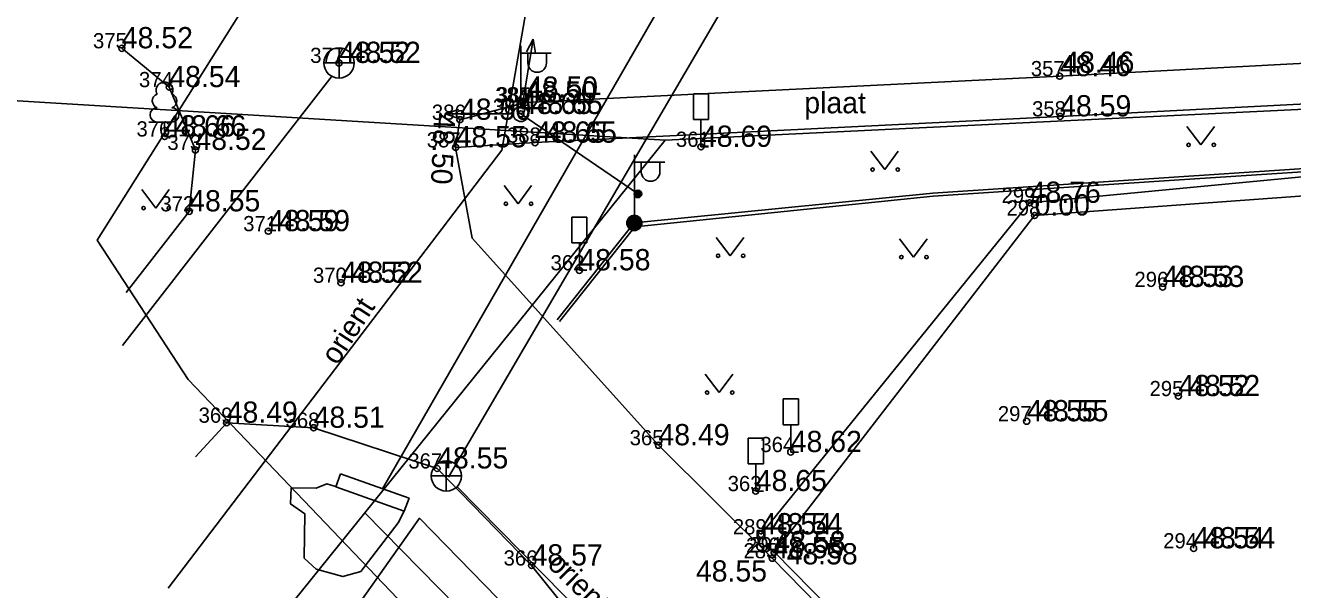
# Model space of a CAD drawing. Extents: x 640876 to 641418, y 6455595 to 6456085.
# Drawn here: x 641063.77 to 641105.51, y 6455977.11 to 6455995.7 of the extents above; entities that cross this region are included whole.
import ezdxf

# ---------------------------------------------------------------- set-up
doc = ezdxf.new("R2010")
doc.units = 0
for name, color, linetype in [('AED', 7, 'Continuous'), ('HALJASTUS', 7, 'Continuous'), ('KKAEV', 7, 'Continuous'), ('KORGUS', 7, 'Continuous'), ('KPKAABEL', 7, 'Continuous'), ('KTRASS', 7, 'Continuous'), ('LIIKLUS', 7, 'Continuous'), ('MOOTKORG', 7, 'Continuous'), ('MOOTMPUNKT', 7, 'Continuous'), ('MOOTNR', 7, 'Continuous'), ('MOOTPIIR', 7, 'Continuous'), ('MPKAABEL', 7, 'Continuous'), ('MPOHULIIN', 7, 'Continuous'), ('PIIR', 7, 'Continuous'), ('POST', 7, 'Continuous'), ('PUU', 7, 'Continuous'), ('SKKAEV', 7, 'Continuous'), ('SKTRASS', 7, 'Continuous'), ('TEE', 7, 'Continuous'), ('TRUUP', 7, 'Continuous'), ('VEEKOGU', 7, 'Continuous')]:
    doc.layers.add(name, color=color, linetype=linetype)

msp = doc.modelspace()

# ---------------------------------------------------------------- linework, layer by layer
at = {"layer": 'AED'}
for p, q in [((641087.869, 6455979.056), (641087.869, 6455978.806)), ((641087.869, 6455979.056), (641088.119, 6455979.056)), ((641088.119, 6455979.056), (641088.119, 6455978.806)), ((641087.869, 6455978.806), (641088.119, 6455978.806))]:
    msp.add_line(p, q, dxfattribs=at)
for points in [[(641087.994, 6455978.931), (641096.846, 6455989.854), (641117.445, 6455991.822), (641132.506, 6455992.659), (641144.443, 6455993.343), (641153.401, 6455993.722)], [(641083.796, 6455973.39), (641083.187, 6455972.863), (641076.75, 6455979.46), (641073.84, 6455975.34)], [(641149.47, 6455968.396), (641146.41, 6455975.887), (641122.837, 6455974.363), (641106.897, 6455973.309), (641093.89, 6455972.505), (641088.371, 6455978.142)]]:
    msp.add_lwpolyline(points, dxfattribs=at)
at = {"layer": 'HALJASTUS'}
for p, q in [((641102.021, 6455992.369), (641102.484, 6455991.763)), ((641102.484, 6455991.763), (641102.93, 6455992.369)), ((641091.612, 6455991.558), (641092.075, 6455990.951)), ((641092.075, 6455990.951), (641092.52, 6455991.558)), ((641079.535, 6455990.431), (641079.998, 6455989.824)), ((641079.998, 6455989.824), (641080.444, 6455990.431)), ((641067.6, 6455990.291), (641068.063, 6455989.684)), ((641068.063, 6455989.684), (641068.509, 6455990.291)), ((641086.52, 6455988.717), (641086.983, 6455988.111)), ((641086.983, 6455988.111), (641087.429, 6455988.717)), ((641092.558, 6455988.672), (641093.021, 6455988.066)), ((641093.021, 6455988.066), (641093.467, 6455988.672)), ((641086.159, 6455984.209), (641086.622, 6455983.602)), ((641086.622, 6455983.602), (641087.068, 6455984.209))]:
    msp.add_line(p, q, dxfattribs=at)
for centre in [(641102.083, 6455991.763), (641102.912, 6455991.763), (641091.674, 6455990.951), (641092.503, 6455990.951), (641067.662, 6455989.684), (641068.491, 6455989.684), (641079.597, 6455989.824), (641080.426, 6455989.824), (641086.582, 6455988.111), (641087.411, 6455988.111), (641092.62, 6455988.066), (641093.449, 6455988.066), (641086.221, 6455983.602), (641087.05, 6455983.602)]:
    msp.add_circle(centre, 0.055, dxfattribs=at)
at = {"layer": 'KKAEV'}
for p, q in [((641074.101, 6455993.964), (641074.101, 6455994.964)), ((641073.601, 6455994.464), (641074.601, 6455994.464))]:
    msp.add_line(p, q, dxfattribs=at)
msp.add_circle((641074.101, 6455994.464), 0.5, dxfattribs=at)
at = {"layer": 'KORGUS'}
for centre in [(641074.101, 6455994.464), (641097.835, 6455994.027), (641080.246, 6455993.162), (641080.092, 6455992.782), (641078.083, 6455992.591), (641068.353, 6455992.04), (641080.556, 6455991.837), (641071.768, 6455988.92), (641074.166, 6455987.22), (641101.223, 6455987.082), (641101.745, 6455983.485), (641096.748, 6455982.656), (641087.994, 6455978.931), (641088.371, 6455978.142), (641088.438, 6455978.34), (641102.244, 6455978.47)]:
    msp.add_circle(centre, 0.1, dxfattribs=at)
at = {"layer": 'KPKAABEL'}
msp.add_lwpolyline([(641068.476, 6455977.159), (641079.463, 6455991.588), (641081.251, 6456001.896), (641083.656, 6456018.212)], dxfattribs=at)
at = {"layer": 'KTRASS'}
for points in [[(641073.874, 6455994.035), (641066.967, 6455985.152)], [(641106.77, 6455951.257), (641077.988, 6455980.501)]]:
    msp.add_lwpolyline(points, dxfattribs=at)
at = {"layer": 'LIIKLUS'}
for p, q in [((641085.77, 6455993.449), (641085.77, 6455992.599)), ((641086.27, 6455993.449), (641085.77, 6455993.449)), ((641086.27, 6455993.449), (641086.27, 6455992.599)), ((641086.27, 6455992.599), (641085.77, 6455992.599)), ((641086.02, 6455992.599), (641086.02, 6455991.699)), ((641086.27, 6455991.699), (641086.02, 6455991.699)), ((641081.766, 6455989.381), (641081.766, 6455988.531)), ((641082.266, 6455989.381), (641081.766, 6455989.381)), ((641082.266, 6455989.381), (641082.266, 6455988.531)), ((641082.266, 6455988.531), (641081.766, 6455988.531)), ((641082.016, 6455988.531), (641082.016, 6455987.631)), ((641082.266, 6455987.631), (641082.016, 6455987.631)), ((641088.728, 6455983.392), (641088.728, 6455982.542)), ((641089.228, 6455983.392), (641088.728, 6455983.392)), ((641089.228, 6455983.392), (641089.228, 6455982.542)), ((641089.228, 6455982.542), (641088.728, 6455982.542)), ((641088.978, 6455982.542), (641088.978, 6455981.642)), ((641087.575, 6455982.105), (641087.575, 6455981.255)), ((641088.075, 6455982.105), (641087.575, 6455982.105)), ((641088.075, 6455982.105), (641088.075, 6455981.255)), ((641089.228, 6455981.642), (641088.978, 6455981.642)), ((641088.075, 6455981.255), (641087.575, 6455981.255)), ((641087.825, 6455981.255), (641087.825, 6455980.355)), ((641088.075, 6455980.355), (641087.825, 6455980.355))]:
    msp.add_line(p, q, dxfattribs=at)
at = {"layer": 'MOOTMPUNKT'}
for centre in [(641066.946, 6455994.946), (641074.101, 6455994.464), (641097.835, 6455994.027), (641068.51, 6455993.666), (641080.246, 6455993.162), (641080.247, 6455993.161), (641080.092, 6455992.783), (641080.092, 6455992.782), (641078.083, 6455992.591), (641097.851, 6455992.703), (641068.353, 6455992.04), (641069.371, 6455991.597), (641077.94, 6455991.681), (641080.556, 6455991.837), (641086.02, 6455991.699), (641096.846, 6455989.854), (641069.165, 6455989.573), (641097.01, 6455989.437), (641071.768, 6455988.92), (641082.016, 6455987.631), (641074.166, 6455987.22), (641101.223, 6455987.082), (641101.745, 6455983.485), (641070.4, 6455982.608), (641073.264, 6455982.442), (641096.748, 6455982.656), (641084.621, 6455981.866), (641088.978, 6455981.642), (641077.332, 6455981.101), (641087.825, 6455980.355), (641087.994, 6455978.931), (641088.371, 6455978.142), (641088.432, 6455978.324), (641088.438, 6455978.34), (641102.244, 6455978.47), (641080.443, 6455977.904)]:
    msp.add_circle(centre, 0.1, dxfattribs=at)
at = {"layer": 'MOOTPIIR'}
msp.add_lwpolyline([(641060.916, 6455895.936), (641100.061, 6455950.482), (641099.586, 6455952.159), (641069.132, 6455984.035), (641066.132, 6455988.623), (641076.463, 6456005.049), (641230.642, 6456010.048), (641237.36, 6455995.24), (641237.24, 6455992.81), (641236.258, 6455990.888), (641229.041, 6455971.315), (641203.026, 6455909.57), (641225.257, 6455906.847), (641239.512, 6455898.491), (641200.195, 6455851.697), (641192.016, 6455859.099), (641169.785, 6455829.138), (641192.025, 6455807.568), (641252.96, 6455758.075), (641231.388, 6455736.74), (641191.474, 6455775.975), (641152.419, 6455787.914), (641136.351, 6455788.307), (641049.066, 6455856.043)], dxfattribs=at)
at = {"layer": 'MPKAABEL'}
for points in [[(641081.282, 6455986.001), (641083.826, 6455989.191), (641093.656, 6455990.177), (641101.434, 6455990.689), (641109.211, 6455991.201), (641116.735, 6455992.286), (641117.253, 6455992.438), (641137.02, 6455993.508), (641152.446, 6455994.375), (641152.745, 6455994.399), (641153.077, 6455993.956), (641153.192, 6455989.529), (641153.743, 6455971.272), (641153.877, 6455968.765), (641154.087, 6455964.787), (641154.134, 6455960.265)], [(641154.034, 6455960.264), (641153.95, 6455965.518), (641153.778, 6455968.761), (641153.643, 6455971.268), (641153.102, 6455989.126), (641152.978, 6455993.905), (641152.599, 6455994.224), (641152.147, 6455994.252), (641142.791, 6455993.73), (641131.26, 6455993.087), (641117.217, 6455992.367), (641116.76, 6455992.188), (641112.991, 6455991.645), (641109.221, 6455991.101), (641101.443, 6455990.589), (641093.665, 6455990.077), (641088.757, 6455989.569), (641083.848, 6455989.06), (641081.36, 6455985.939)]]:
    msp.add_lwpolyline(points, dxfattribs=at)
at = {"layer": 'MPOHULIIN'}
for p, q in [((641080.132, 6455993.03), (641080.492, 6455995.251)), ((641080.492, 6455995.251), (641080.271, 6455994.83)), ((641080.492, 6455995.251), (641080.566, 6455994.782)), ((641077.592, 6455992.785), (641078.044, 6455992.933)), ((641077.592, 6455992.785), (641078.043, 6455992.634)), ((641079.842, 6455992.783), (641077.592, 6455992.785)), ((641080.092, 6455992.783), (641080.092, 6455992.783)), ((641080.092, 6455992.783), (641080.092, 6455992.783))]:
    msp.add_line(p, q, dxfattribs=at)
at = {"layer": 'PIIR'}
for points in [[(640981.25, 6456014.49), (641018.11, 6456020.73), (641048.89, 6456017.91), (641071.8, 6456014.51), (641086.43, 6456012.78), (641194.48, 6456014.88), (641224.33, 6456016.64), (641234.96, 6456017.83), (641241.97, 6456004.88), (641237.36, 6455995.24), (641222.58, 6455998.61), (641084.84, 6455991.92), (641061.51, 6455993.34), (640998.61, 6455989.99), (640969.54, 6455988.44)], [(641222.58, 6455998.61), (641237.36, 6455995.24), (641235.34, 6455991.29), (641228.11, 6455971.68), (641220.5, 6455953.19), (641213.41, 6455936.25), (641201.58, 6455908.74), (641224.93, 6455905.88), (641191.87, 6455860.58), (641157.02, 6455885.66), (641160.91, 6455891.99), (641102.26, 6455951.82), (641074.95, 6455979.64), (641084.84, 6455991.92)], [(641074.95, 6455979.64), (641102.26, 6455951.82), (641075.14, 6455914.24), (641043, 6455940)]]:
    msp.add_lwpolyline(points, close=True, dxfattribs=at)
msp.add_lwpolyline([(641061.51, 6455993.34), (641084.84, 6455991.92), (641074.95, 6455979.64), (641043, 6455940)], dxfattribs=at)
at = {"layer": 'POST'}
for p, q in [((641080.092, 6455993.033), (641080.092, 6455995.033)), ((641080.092, 6455994.783), (641081.092, 6455994.783)), ((641080.318, 6455994.462), (641080.318, 6455994.783)), ((641080.931, 6455994.462), (641080.931, 6455994.783)), ((641080.092, 6455992.783), (641080.092, 6455992.783)), ((641083.828, 6455989.441), (641083.828, 6455991.441)), ((641083.828, 6455991.191), (641084.828, 6455991.191)), ((641084.055, 6455990.87), (641084.055, 6455991.191)), ((641084.668, 6455990.87), (641084.668, 6455991.191)), ((641083.828, 6455989.191), (641083.828, 6455989.191))]:
    msp.add_line(p, q, dxfattribs=at)
msp.add_lwpolyline([(641083.961, 6455990.137), (641080.092, 6455992.783)], dxfattribs=at)
for centre, radius in [((641080.092, 6455992.782), 0.25), ((641083.943, 6455990.15), 0.125), ((641083.943, 6455990.15), 0.105), ((641083.943, 6455990.15), 0.0851), ((641083.943, 6455990.15), 0.0651), ((641083.943, 6455990.15), 0.0451), ((641083.943, 6455990.15), 0.0251), ((641083.943, 6455990.15), 0.00511), ((641083.826, 6455989.191), 0.25), ((641083.826, 6455989.191), 0.225), ((641083.826, 6455989.191), 0.2), ((641083.826, 6455989.191), 0.175), ((641083.826, 6455989.191), 0.15), ((641083.826, 6455989.191), 0.125), ((641083.826, 6455989.191), 0.1), ((641083.826, 6455989.191), 0.075), ((641083.826, 6455989.191), 0.05), ((641083.826, 6455989.191), 0.025)]:
    msp.add_circle(centre, radius, dxfattribs=at)
for centre in [(641080.625, 6455994.462), (641084.361, 6455990.87)]:
    msp.add_arc(centre, 0.306, 180, 0, dxfattribs=at)
at = {"layer": 'PUU'}
for p, q in [((641068.593, 6455992.515), (641068.113, 6455992.515)), ((641068.353, 6455992.04), (641068.353, 6455992.515)), ((641068.733, 6455992.04), (641068.353, 6455992.04))]:
    msp.add_line(p, q, dxfattribs=at)
for centre, radius, start, end in [((641068.353, 6455993.56), 0.277, 332.5799, 207.4201), ((641068.183, 6455993.212), 0.233, 109.0217, 253.1415), ((641068.523, 6455993.212), 0.233, 286.8508, 70.9859), ((641068.115, 6455992.752), 0.238, 90.0016, 269.3953), ((641068.59, 6455992.752), 0.238, 270.6047, 89.9984)]:
    msp.add_arc(centre, radius, start, end, dxfattribs=at)
at = {"layer": 'SKKAEV'}
for p, q in [((641077.634, 6455980.354), (641077.634, 6455981.354)), ((641077.134, 6455980.854), (641078.134, 6455980.854))]:
    msp.add_line(p, q, dxfattribs=at)
msp.add_circle((641077.634, 6455980.854), 0.5, dxfattribs=at)
at = {"layer": 'SKTRASS'}
msp.add_lwpolyline([(641091.986, 6456005.257), (641077.702, 6455980.813)], dxfattribs=at)
at = {"layer": 'TEE'}
for points in [[(641088.432, 6455978.324), (641097.01, 6455989.437), (641117.484, 6455990.932), (641132.837, 6455992.048), (641144.43, 6455992.887), (641153.501, 6455993.325), (641154.822, 6455993.407), (641154.653, 6455994.333), (641154.316, 6455995.079), (641153.74, 6455995.681), (641153.065, 6455996.145), (641151.601, 6455996.628), (641150.727, 6455996.717), (641135.038, 6455995.912), (641116.951, 6455995.037), (641097.835, 6455994.027), (641080.247, 6455993.161), (641080.246, 6455993.162), (641078.083, 6455992.591), (641077.94, 6455991.681), (641080.556, 6455991.837)], [(641153.501, 6455993.325), (641153.465, 6455993.996), (641152.772, 6455994.709), (641151.844, 6455995.148), (641150.896, 6455995.393), (641135.023, 6455994.601), (641116.405, 6455993.654), (641097.851, 6455992.703), (641080.556, 6455991.837)], [(641067.093, 6455986.898), (641069.165, 6455989.573), (641069.371, 6455991.597), (641068.51, 6455993.666), (641066.946, 6455994.946)], [(641088.371, 6455978.142), (641084.621, 6455981.866), (641078.484, 6455988.693), (641077.94, 6455991.681)], [(641107.214, 6455949.459), (641105.82, 6455951.112), (641104.302, 6455952.658), (641094.195, 6455963.079), (641083.782, 6455973.751), (641080.443, 6455977.904), (641077.332, 6455981.101), (641073.264, 6455982.442), (641070.4, 6455982.608), (641069.377, 6455981.48)], [(641088.438, 6455978.34), (641093.974, 6455972.705), (641102.503, 6455973.228), (641118.732, 6455974.289), (641132.709, 6455975.218), (641148.246, 6455976.21), (641160.465, 6455968.928), (641160.995, 6455968.496)]]:
    msp.add_lwpolyline(points, dxfattribs=at)
at = {"layer": 'TRUUP'}
for points in [[(641090.307, 6456006.129), (641075.531, 6455980.433)], [(641074.148, 6455980.924), (641076.408, 6455980.122), (641076.248, 6455979.7), (641073.997, 6455980.499), (641074.148, 6455980.924)]]:
    msp.add_lwpolyline(points, dxfattribs=at)
at = {"layer": 'VEEKOGU'}
msp.add_lwpolyline([(641076.248, 6455979.7), (641076.043, 6455979.314), (641074.816, 6455977.712), (641074.228, 6455977.539), (641073.345, 6455977.783), (641072.956, 6455978.149), (641072.969, 6455979.611), (641072.506, 6455979.933), (641072.527, 6455980.461), (641073.346, 6455980.458), (641073.701, 6455980.591), (641073.988, 6455980.502)], dxfattribs=at)

# ---------------------------------------------------------------- texts
at = {"layer": 'KORGUS'}
for s, p in [('48.52', (641074.451, 6455994.464)), ('48.46', (641097.954, 6455994.138)), ('48.50', (641080.287, 6455993.318)), ('48.65', (641080.442, 6455992.782)), ('48.66', (641068.703, 6455992.04)), ('48.65', (641080.906, 6455991.837)), ('48.59', (641072.118, 6455988.92)), ('48.52', (641074.516, 6455987.22)), ('48.53', (641101.573, 6455987.082)), ('48.52', (641102.095, 6455983.485)), ('48.55', (641097.098, 6455982.656)), ('48.54', (641088.344, 6455978.931)), ('48.54', (641102.594, 6455978.47)), ('48.58', (641088.84, 6455977.941)), ('48.55', (641085.854, 6455977.375))]:
    msp.add_text(s, height=0.7, dxfattribs=at).set_placement(p)
msp.add_text('48.50', height=0.7, rotation=267.341, dxfattribs=at).set_placement((641077.235, 6455992.815))
at = {"layer": 'KPKAABEL'}
msp.add_text('orient', height=0.7, rotation=57.0152, dxfattribs=at).set_placement((641074.039, 6455984.473))
at = {"layer": 'MOOTKORG'}
for s, p in [('48.52', (641066.946, 6455994.946)), ('48.52', (641074.101, 6455994.464)), ('48.46', (641097.835, 6455994.027)), ('48.54', (641068.51, 6455993.666)), ('48.50', (641080.246, 6455993.162)), ('48.50', (641080.247, 6455993.161)), ('48.50', (641078.083, 6455992.591)), ('48.65', (641080.092, 6455992.783)), ('48.65', (641080.092, 6455992.782)), ('48.59', (641097.851, 6455992.703)), ('48.66', (641068.353, 6455992.04)), ('48.55', (641077.94, 6455991.681)), ('48.65', (641080.556, 6455991.837)), ('48.69', (641086.02, 6455991.699)), ('48.52', (641069.371, 6455991.597)), ('48.76', (641096.846, 6455989.854)), ('48.55', (641069.165, 6455989.573)), ('0.00', (641097.01, 6455989.437)), ('48.59', (641071.768, 6455988.92)), ('48.58', (641082.016, 6455987.631)), ('48.52', (641074.166, 6455987.22)), ('48.53', (641101.223, 6455987.082)), ('48.52', (641101.745, 6455983.485)), ('48.49', (641070.4, 6455982.608)), ('48.55', (641096.748, 6455982.656)), ('48.51', (641073.264, 6455982.442)), ('48.49', (641084.621, 6455981.866)), ('48.62', (641088.978, 6455981.642)), ('48.55', (641077.332, 6455981.101)), ('48.65', (641087.825, 6455980.355)), ('48.54', (641087.994, 6455978.931)), ('48.58', (641088.432, 6455978.324)), ('48.58', (641088.438, 6455978.34)), ('48.54', (641102.244, 6455978.47)), ('48.57', (641080.443, 6455977.904)), ('48.55', (641088.371, 6455978.142))]:
    msp.add_text(s, height=0.7, dxfattribs=at).set_placement(p)
at = {"layer": 'MOOTNR'}
for s, p in [('375', (641065.996, 6455994.946)), ('377', (641073.151, 6455994.464)), ('357', (641096.885, 6455994.027)), ('374', (641067.51, 6455993.666)), ('384', (641079.247, 6455993.161)), ('385', (641079.296, 6455993.162)), ('390', (641079.167, 6455992.783)), ('389', (641079.167, 6455992.782)), ('386', (641077.158, 6455992.591)), ('358', (641096.926, 6455992.703)), ('376', (641067.428, 6455992.04)), ('373', (641068.446, 6455991.597)), ('387', (641076.99, 6455991.681)), ('388', (641079.631, 6455991.837)), ('361', (641085.195, 6455991.699)), ('299', (641095.921, 6455989.854)), ('372', (641068.215, 6455989.573)), ('298', (641096.085, 6455989.437)), ('371', (641070.943, 6455988.92)), ('362', (641081.066, 6455987.631)), ('370', (641073.242, 6455987.22)), ('296', (641100.298, 6455987.082)), ('295', (641100.795, 6455983.485)), ('369', (641069.475, 6455982.608)), ('368', (641072.339, 6455982.442)), ('297', (641095.798, 6455982.656)), ('365', (641083.672, 6455981.866)), ('364', (641087.978, 6455981.642)), ('367', (641076.382, 6455981.101)), ('363', (641086.9, 6455980.355)), ('289', (641087.07, 6455978.931)), ('285', (641087.421, 6455978.142)), ('290', (641087.507, 6455978.324)), ('291', (641087.613, 6455978.34)), ('294', (641101.244, 6455978.47)), ('366', (641079.519, 6455977.904))]:
    msp.add_text(s, height=0.5, dxfattribs=at).set_placement(p)
at = {"layer": 'SKTRASS'}
msp.add_text('orient.', height=0.7, rotation=315.6107, dxfattribs=at).set_placement((641080.924, 6455977.91))
at = {"layer": 'TEE'}
msp.add_text('plaat', height=0.7, dxfattribs=at).set_placement((641089.424, 6455992.805))

doc.saveas('drawing.dxf')
